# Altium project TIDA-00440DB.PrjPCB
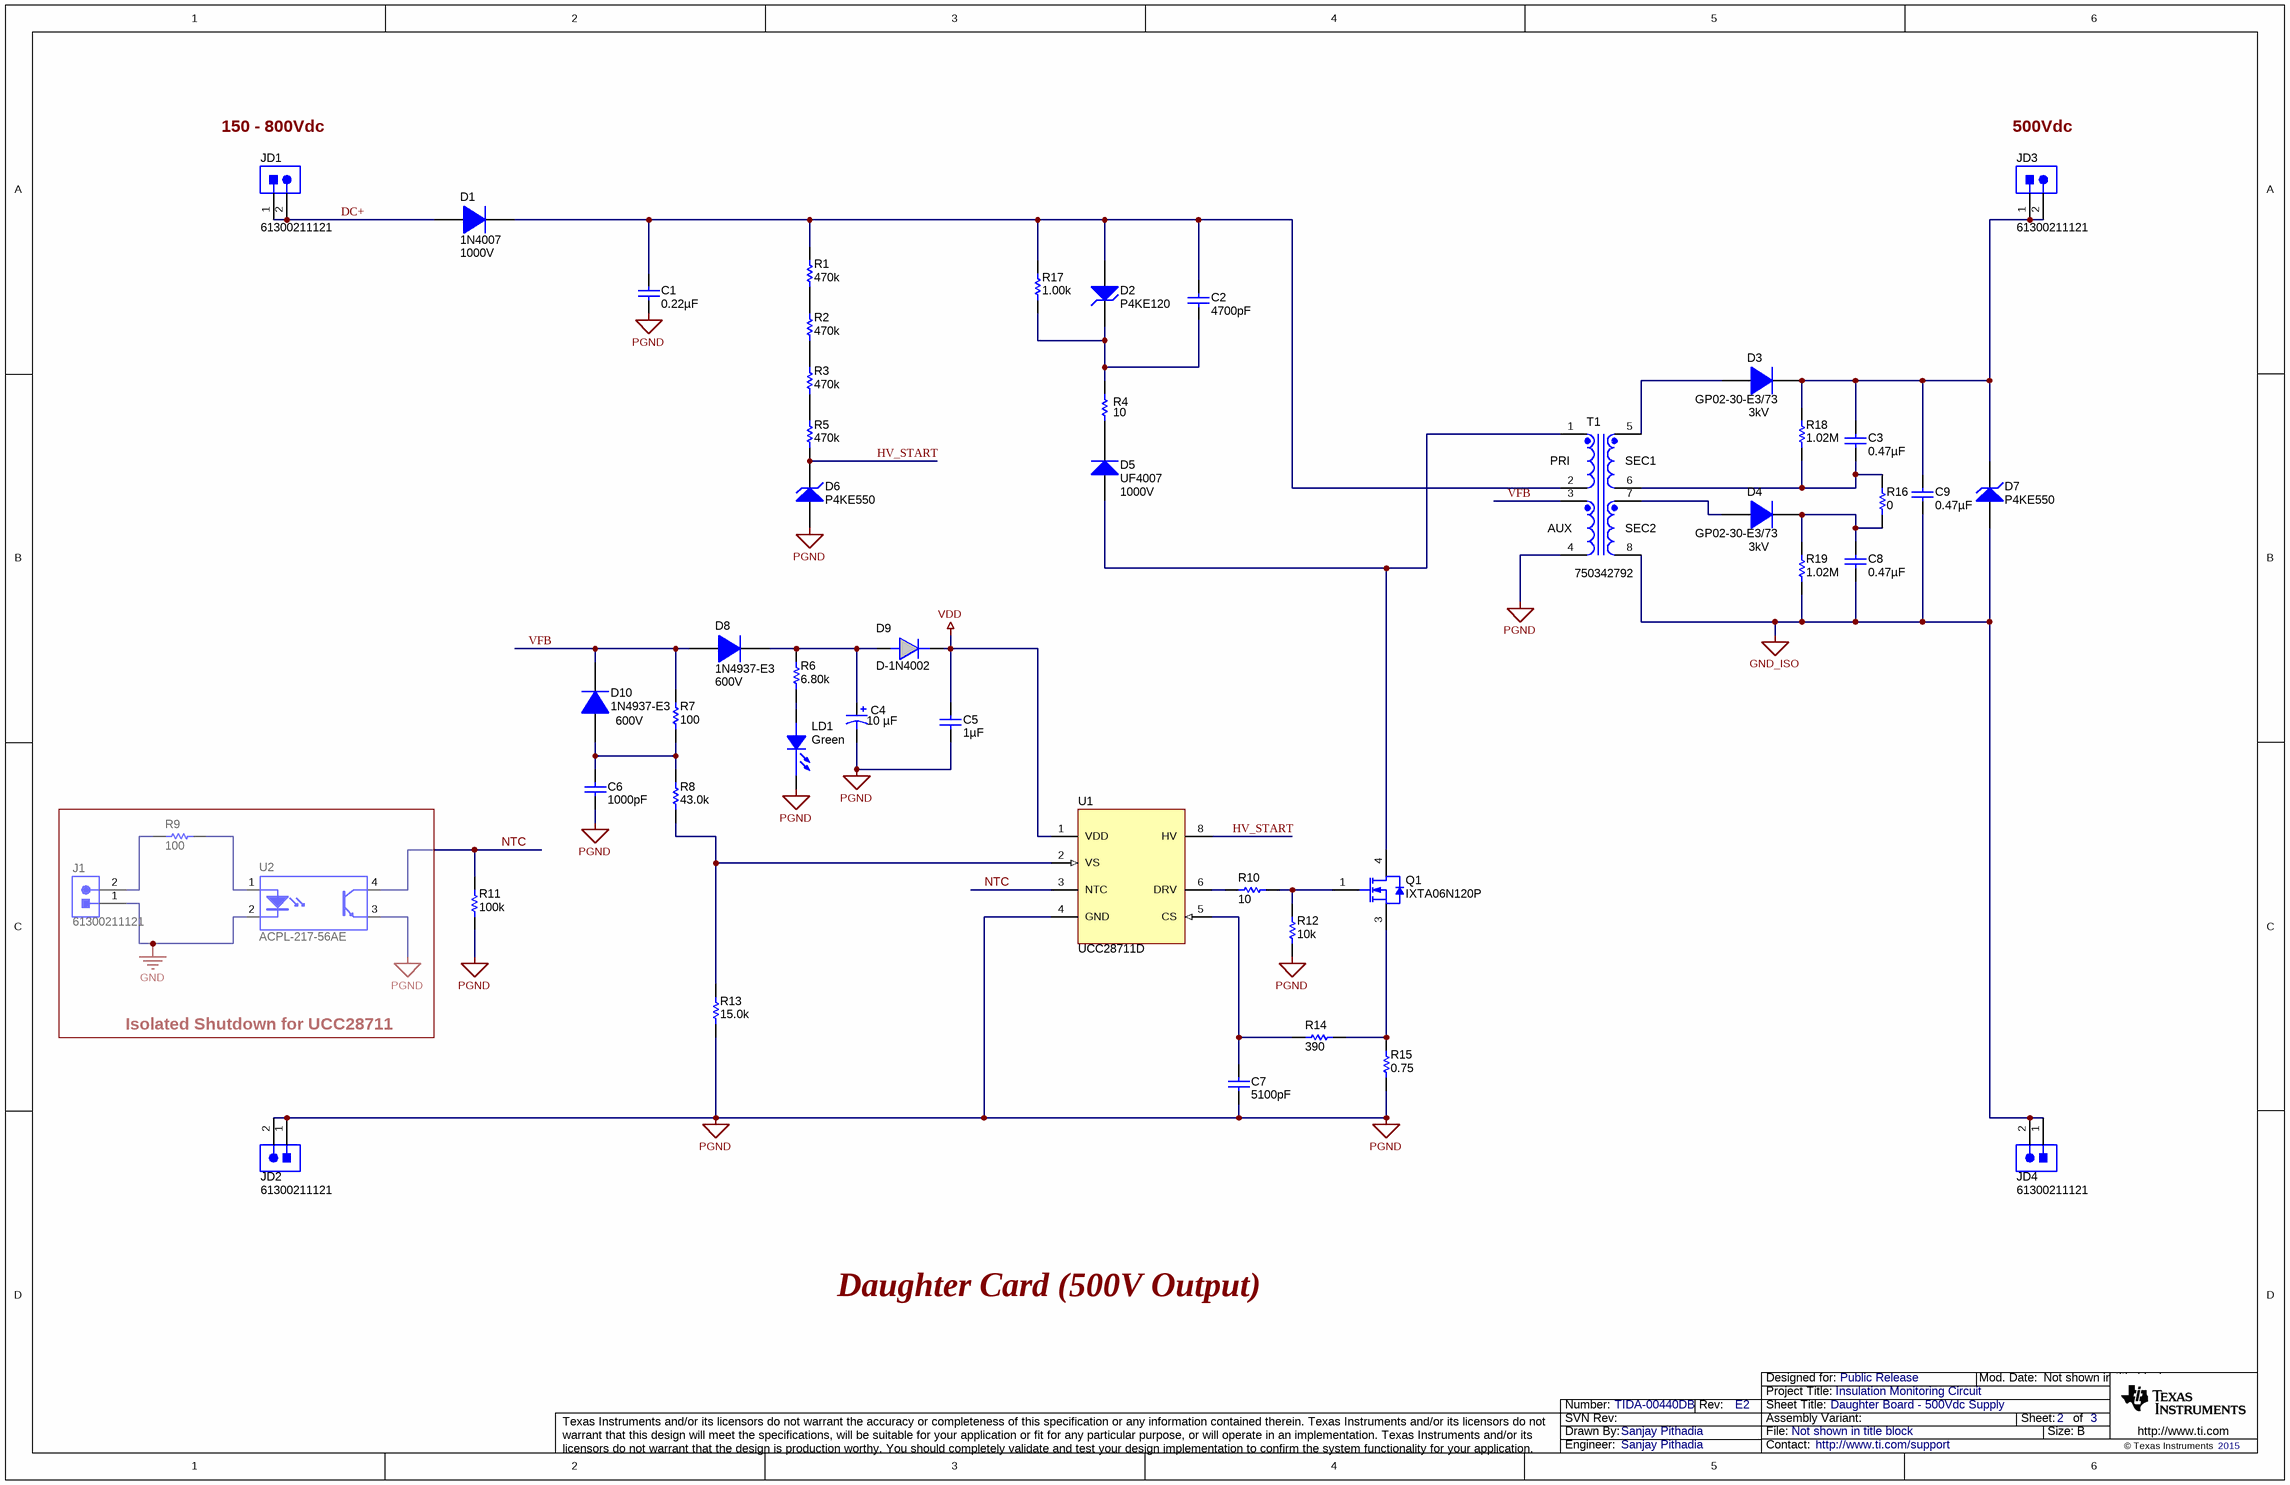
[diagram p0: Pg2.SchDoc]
CopyrightYear: 2015; PCB_Layout: Manjunath M; PCB_Rev: E2; PRJ_Customer: Public Release; PRJ_Engineer: Sanjay Pithadia; PRJ_Number: TIDA-00440DB; PRJ_Title: Insulation Monitoring Circuit; SCH_Rev: E2; TechSupport: http://www.ti.com/support
3 sheets, 56 parts. Net scope: global (net labels, ports and power ports of the same name join across sheets).
Board file: TIDA-00440DB.PcbDoc
Sheets:
  Pg1-Cover.SchDoc
  Pg2.SchDoc
  Pg3_Hardware_ANSI-B.SchDoc

## Sheet Pg1-Cover.SchDoc
size 431 x 279 mm; Date: Not shown in title block; ApprovedBy: Not shown in title block; CheckedBy: Not shown in title block; Author: Not shown in title block; CompanyName: Not shown in title block; DrawnBy: Sanjay Pithadia; Engineer: Not shown in title block; Organization: Not shown in title block; Address1: Not shown in title block; Address2: Not shown in title block; Address3: Not shown in title block; Address4: Not shown in title block; DocumentNumber: 1; Revision: Use project parameter SCH_Rev; SheetNumber: 1; SheetTotal: 3; PageSetup: Record=PageOptions|CenterHorizontal=True|CenterVertical=True|PrintScale=1.00|XCorrection=1.00|YCorrection=1.00|PrintKind=0|BorderSize=5000000|LeftOffset=0|BottomOffset=0|Orientation=2|PaperLength=1000|PaperWidth=1000|Scale=100|PaperSource=15|PrintQuality=600|MediaType=1|DitherType=10|PaperKind=Letter|PrintScaleMode=1

## Sheet Pg2.SchDoc: Daughter Board - 500Vdc Supply
size 431 x 279 mm; Date: Not shown in title block; ApprovedBy: Not shown in title block; CheckedBy: Not shown in title block; Author: Not shown in title block; CompanyName: Not shown in title block; DrawnBy: Sanjay Pithadia; Engineer: Not shown in title block; Organization: Not shown in title block; Address1: Not shown in title block; Address2: Not shown in title block; Address3: Not shown in title block; Address4: Not shown in title block; DocumentNumber: 4; Revision: Use project parameter SCH_Rev; SheetNumber: 2; SheetTotal: 3; PageSetup: Record=PageOptions|CenterHorizontal=True|CenterVertical=True|PrintScale=1.00|XCorrection=1.00|YCorrection=1.00|PrintKind=0|BorderSize=5000000|LeftOffset=0|BottomOffset=0|Orientation=2|PaperLength=1000|PaperWidth=1000|Scale=100|PaperSource=15|PrintQuality=600|MediaType=1|DitherType=10|PaperKind=Letter|PrintScaleMode=1

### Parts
C1  ValueDisplayed: 0.22µF  [B32653_2650x2050x1100]  (hidden comment: B32653A224J)
C2  ValueDisplayed: 4700pF  [1206]  (hidden comment: GRM31BR73A472KW01L)
C3  ValueDisplayed: 0.47µF  [1812]  (hidden comment: C4532X7T2W474K230KA)
C4  ValueDisplayed: 10 µF  [CAPPR2-5x11]  (hidden comment: UVR1V100MDD1TA)
C5  ValueDisplayed: 1µF  [0805_HV]  (hidden comment: GMK212B7105KG-T)
C6  ValueDisplayed: 1000pF  [0805_HV]  (hidden comment: C0805C102K1RACTU)
C7  ValueDisplayed: 5100pF  [0805_HV]  (hidden comment: GRM2195C1H512JA01D)
C8  ValueDisplayed: 0.47µF  [1812]  (hidden comment: C4532X7T2W474K230KA)
C9  ValueDisplayed: 0.47µF  [2220]  (hidden comment: CGA9P1X7T2J474K250KE)
D1  1N4007  value 1000V  [DO-41]
D2  P4KE120  [DO-41]
D3  GP02-30-E3/73  value 3kV  [DO-41]
D4  GP02-30-E3/73  value 3kV  [DO-41]
D5  UF4007  value 1000V  [DO-204AC_VERT]
D6  P4KE550  [DO-41]
D7  P4KE550  [DO-41]
D8  1N4937-E3  value 600V  [DO-41]
D9  D-1N4002  [DO-41]
D10  1N4937-E3  value 600V  [DO-41]
J1  61300211121  [WURTH_61300211121]
JD1  61300211121  [WURTH_61300211121]
JD2  61300211121  [WURTH_61300211121]
JD3  61300211121  [WURTH_61300211121]
JD4  61300211121  [WURTH_61300211121]
LD1  value Green  [LED0603AA]  (hidden comment: LED_LG L29K-G2J1-24-Z)
Q1  IXTA06N120P  [DDPAK]
R1  value 470k  [1206]  (hidden comment: RC1206FR-07470KL)
R2  value 470k  [1206]  (hidden comment: RC1206FR-07470KL)
R3  value 470k  [1206]  (hidden comment: RC1206FR-07470KL)
R4  value 10  [2512M]  (hidden comment: ERJ-1TYJ100U)
R5  value 470k  [1206]  (hidden comment: RC1206FR-07470KL)
R6  value 6.80k  [0805_HV]  (hidden comment: RG2012P-682-B-T5)
R7  ValueDisplayed: 100  [0805_HV]  (hidden comment: CRCW0805100RFKEA)
R8  ValueDisplayed: 43.0k  [0805_HV]  (hidden comment: RG2012P-433-B-T5)
R9  ValueDisplayed: 100  [0805_HV]  (hidden comment: CRCW0805100RFKEA)
R10  ValueDisplayed: 10  [0805_HV]  (hidden comment: CRCW080510R0JNEA)
R11  ValueDisplayed: 100k  [0805_HV]  (hidden comment: CRCW0805100KFKEA)
R12  ValueDisplayed: 10k  [0805_HV]  (hidden comment: CRCW080510K0JNEA)
R13  ValueDisplayed: 15.0k  [0805_HV]  (hidden comment: CRCW080515K0FKEA)
R14  ValueDisplayed: 390  [0805_HV]  (hidden comment: RG2012P-391-B-T5)
R15  ValueDisplayed: 0.75  [2010]  (hidden comment: CSRN2010FKR750)
R16  ValueDisplayed: 0  [1206]  (hidden comment: CRCW12060000Z0EA)
R17  ValueDisplayed: 1.00k  [2512]  (hidden comment: CRCW25121K00FKEG)
R18  ValueDisplayed: 1.02M  [1206]  (hidden comment: CRCW12061M02FKEA)
R19  ValueDisplayed: 1.02M  [1206]  (hidden comment: CRCW12061M02FKEA)
T1  750342792  [Wurth_750342792]
U1  UCC28711D  [D0007A_N]
U2  ACPL-217-56AE  [SO4]

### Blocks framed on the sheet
Isolated Shutdown for UCC28711: J1 R9 U2

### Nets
GND: J1.1 U2.2(K)
GND_ISO: C8.2 C9.2 D7.2(A) JD4.1 JD4.2 R19.1 T1.8
PGND: C1.2 C4.2(-) C5.2 C6.2 C7.2 D6.2(A) JD2.1 JD2.2 LD1.1(C) R11.1 R12.1 R13.1 R15.2 T1.4 U1.4(GND) U2.3(E)
VDD: C5.1 D9.1(C) U1.1(VDD)
DC+: D1.2(A) JD1.1 JD1.2
HV_START: D6.1(K) R5.1 U1.8(HV)
NTC: R11.2 U1.3(NTC) U2.4(C)
VFB: D8.2(A) D10.1(K) R7.2 T1.3
NetC1_1: C1.1 C2.1 D1.1(K) D2.2(A) R1.2 R17.2 T1.2
NetC2_2: C2.2 D2.1(K) R4.2 R17.1
NetC3_1: C3.1 C9.1 D3.1(K) D7.1(K) JD3.1 JD3.2 R18.2
NetC3_2: C3.2 R16.2 R18.1 T1.6
NetC4_1: C4.1(+) D8.1(K) D9.2(A) R6.2
NetC6_1: C6.1 D10.2(A) R7.1 R8.2
NetC7_1: C7.1 R14.1 U1.5(CS)
NetC8_1: C8.1 D4.1(K) R16.1 R19.2
NetD3_2: D3.2(A) T1.5
NetD4_2: D4.2(A) T1.7
NetD5_1: D5.1(K) R4.1
NetD5_2: D5.2(A) Q1.4(D) T1.1
NetJ1_2: J1.2 R9.1
NetLD1_2: LD1.2(A) R6.1
NetQ1_1: Q1.1(G) R10.2 R12.2
NetQ1_3: Q1.3(S) R14.2 R15.1
NetR1_1: R1.1 R2.2
NetR2_1: R2.1 R3.2
NetR3_1: R3.1 R5.2
NetR8_1: R8.1 R13.2 U1.2(VS)
NetR9_2: R9.2 U2.1(A)
NetR10_1: R10.1 U1.6(DRV)

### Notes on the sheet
- 150 - 800Vdc
- 500Vdc
- (near T1) PRI
- (near T1) SEC1
- (near T1) AUX
- (near T1) SEC2
- Daughter Card (500V Output)

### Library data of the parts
C1 = B32653A224J: CAP, Film, 0.22 µF, 1000 V, +/- 5%, TH; Manufacturer: EPCOS Inc; Polarized: N; CompType: Capacitor; Value: 0.22uF; U/M: EA; Cap_F: 0.00000022; Tolerance_%: 5; Value1: Unknown; VDC_V: 1000; Value2: 1000V; TaMin_C: -55; TaMax_C: 110; Cap_Case: 26.5x20.5x11mm
C2 = GRM31BR73A472KW01L: CAP, CERM, 4700pF, 1000V, +/-10%, X7R, 1206; Manufacturer: MuRata; Polarized: N; CompType: Capacitor; U/M: EA; Cap_F: 0.0000000047; Tolerance_%: 10; Value1: Unknown; VDC_V: 1000; TaMin_C: -55; TaMax_C: 125
C3 C8 = GRM43DR72E474KW01L: CAP, CERM, 0.47 µF, 450 V, +/- 10%, X7T, 1812; Manufacturer: TDK Corporation; Polarized: N; CompType: Capacitor; Value: 0.47uF; U/M: EA; Cap_F: 0.00000047; Tolerance_%: 10; Value1: Unknown; VDC_V: 450V; TaMin_C: -55; TaMax_C: 125
C4 = UVR1V100MDD1TA: CAP, AL, 10uF, 35V, +/-20%, TH; Manufacturer: Nichicon; Polarized: Y; CompType: Capacitor; U/M: EA; Cap_F: 0.00001; Tolerance_%: 20; Value1: Unknown; VDC_V: 35; TaMin_C: -40; TaMax_C: 85; Cap_Case: 5x11
C5 = GMK212B7105KG-T: CAP, CERM, 1uF, 35V, +/-10%, X7R, 0805; Manufacturer: Taiyo Yuden; Polarized: N; CompType: Capacitor; U/M: EA; Cap_F: 0.000001; Tolerance_%: 10; Value1: Unknown; VDC_V: 35; TaMin_C: -55; TaMax_C: 125; Cap_Case: 0805
C6 = C0805C102K1RACTU: CAP, CERM, 1000pF, 100V, +/-10%, X7R, 0805; Manufacturer: Kemet; Polarized: N; CompType: Capacitor; U/M: EA; Cap_F: 0.000000001; Tolerance_%: 10; ESR_Ohm: 0.384; Value1: 0.384 ohm; VDC_V: 100; IRMS_A: 0.214; TaMin_C: -55; TaMax_C: 125; Cap_Case: 0805
C7 = GRM2195C1H512JA01D: CAP, CERM, 5100 pF, 50 V, +/- 5%, C0G/NP0, 0805; Manufacturer: MuRata; Polarized: N; CompType: Capacitor; Value: 5100pF; U/M: EA; Cap_F: 0.0000000051; Tolerance_%: 5; Value1: Unknown; VDC_V: 50; Value2: 50V; TaMin_C: -55; TaMax_C: 125; Cap_Case: 0805
C9 = GRM55DR73A104KW01L: CAP, CERM, 0.47 µF, 630 V, +/- 10%, X7T, 2220; Manufacturer: TDK Corporation; Polarized: N; CompType: Capacitor; Value: 0.47uF; U/M: EA; Cap_F: 0.0000001; Tolerance_%: 10; Value1: Unknown; VDC_V: 630V; TempCo: X7R; TaMin_C: -55; TaMax_C: 125
D1 = 1N4007: Diode, P-N, 1000V, 1A, TH; Manufacturer: Fairchild Semiconductor; U/M: EA; Vf_V: 1.1; Value2: 1.1V; Io_A: 1; Vr_V: 1000; TJmax_C: 175; RJC_CperW: 50
D2 = P4KE550: TVS DIODE; Manufacturer: Littelfuse Inc; CompType: Zener; Value: 102V
D3 D4 = 1N4007: Diode, P-N, 3000V, 0.25A, TH; Manufacturer: Vishay; Io_A: 1
D5 = UF4007: DIODE FAST REC 1KV 1A DO41; Manufacturer: Fairchild Semiconductor
D6 D7 = P4KE550: TVS DIODE 495VWM 798VC AXIAL; Manufacturer: Littelfuse Inc; CompType: Zener; Value: 495V
D8 D10 = 1N4937-E3: Diode, Switching, 600V, 1A, TH; Manufacturer: Vishay-Semiconductor; U/M: EA; Vf_V: 1.2; Value2: 1.2V; Io_A: 1; Vr_V: 600; TJmax_C: 150; RJC_CperW: 25
D9 = D-1N4002: Diode, Signal, 100V, 1A; PartNumber: 1N4002; Manufacturer: Diodes; Area: 54000; Value: 1N4002
J1 JD1-JD4 = 61300211121: Header, 2.54 mm, 2x1, Gold, TH; Manufacturer: Wurth Elektronik eiSos; SymbolCreator: a0412235; U/M: EA
LD1 = LED_LG L29K-G2J1-24-Z: LED SmartLED Green 570NM; Manufacturer: OSRAM; SymbolCreator: x0120606
Q1 = IXTA06N120P: MOSFET, N-CH, 1200 V, 0.6 A, DDPAK; Manufacturer: IXYS; Alternate Manufacturer: None; U/M: EA; ChType: N; Value: 1200V; VdsMax_V: 1200; Value1: ? ohm; Value2: 13.3 nC; QgTyp_nC: 13.3; Vgs_V: 20; IdsMax_A: 0.6
R1-R3 R5 = RC1206FR-07470KL: RES, 470k ohm, 1%, 0.25W, 1206; Manufacturer: Yageo America; CompType: Resistor; Res_ohm: 470000; Tolerance_%: 1; Power_W: 0.25; VDC_V: 200; TempCo: 100 ppm/C; U/M: EA
R4 = ERJ-1TYJ100U: RES, 10 ohm, 5%, 1W, 2512; Manufacturer: Panasonic; CompType: Resistor; Value_Code: 10R0; Tolerance_%: 5; Power_W: 1; VDC_V: 200; TempCo: 200 ppm/C; EIA_Code: E24; U/M: EA
R6 = RG2012P-682-B-T5: RES, 6.80k ohm, 0.1%, 0.125W, 0805; Manufacturer: Susumu Co Ltd; CompType: Resistor; Res_ohm: 6800; Value_Code: 6k80; Tolerance_%: 0.1; Power_W: 0.125; VDC_V: 100; TempCo: 25 ppm/C; U/M: EA
R7 R9 = CRCW0805100RFKEA: RES, 100, 1%, 0.125 W, 0805; Manufacturer: Vishay-Dale; CompType: Resistor; Value: 100; Value_Code: 100R; Tolerance_%: 1; Power_W: 0.125; Value2: 0.125W; VDC_V: 150; TempCo: 100 ppm/C; EIA_Code: E96; U/M: EA
R8 = RG2012P-433-B-T5: RES, 43.0 k, 0.1%, 0.125 W, 0805; Manufacturer: Susumu Co Ltd; CompType: Resistor; Value: 43.0k; Res_ohm: 43000; Value_Code: 43k0; Tolerance_%: 0.1; Power_W: 0.125; Value2: 0.125W; VDC_V: 100; TempCo: 25 ppm/C; U/M: EA
R10 = CRCW080510R0JNEA: RES, 10, 5%, 0.125 W, 0805; Manufacturer: Vishay-Dale; CompType: Resistor; Value: 10; Value_Code: 10R0; Tolerance_%: 5; Power_W: 0.125; Value2: 0.125W; VDC_V: 150; TempCo: 200 ppm/C; EIA_Code: E24; U/M: EA
R11 = CRCW0805100KFKEA: RES, 100 k, 1%, 0.125 W, 0805; Manufacturer: Vishay-Dale; CompType: Resistor; Value: 100k; Res_ohm: 100000; Tolerance_%: 1; Power_W: 0.125; Value2: 0.125W; VDC_V: 150; TempCo: 100 ppm/C; EIA_Code: E96; U/M: EA
R12 = CRCW080510K0JNEA: RES, 10 k, 5%, 0.125 W, 0805; Manufacturer: Vishay-Dale; CompType: Resistor; Value: 10k; Res_ohm: 10000; Value_Code: 10k0; Tolerance_%: 5; Power_W: 0.125; Value2: 0.125W; VDC_V: 150; TempCo: 200 ppm/C; EIA_Code: E24; U/M: EA
R13 = CRCW080515K0FKEA: RES, 15.0 k, 1%, 0.125 W, 0805; Manufacturer: Vishay-Dale; CompType: Resistor; Value: 15.0k; Res_ohm: 15000; Value_Code: 15k0; Tolerance_%: 1; Power_W: 0.125; Value2: 0.125W; VDC_V: 150; TempCo: 100 ppm/C; EIA_Code: E96; U/M: EA
R14 = RG2012P-391-B-T5: RES, 390, 0.1%, 0.125 W, 0805; Manufacturer: Susumu Co Ltd; CompType: Resistor; Value: 390; Value_Code: 390R; Tolerance_%: 0.1; Power_W: 0.125; Value2: 0.125W; VDC_V: 100; TempCo: 25 ppm/C; U/M: EA
R15 = CSRN2010FKR750: RES, 0.75, 1%, 1 W, 2010; Manufacturer: Stackpole Electronics Inc; CompType: Resistor; Value: 0.75; Value_Code: R750; Tolerance_%: 1; Value2: 1W; TempCo: 250 ppm/C; EIA_Code: E96; U/M: EA
R16 = CRCW12060000Z0EA: RES, 0, 5%, 0.25 W, 1206; Manufacturer: Vishay-Dale; CompType: Resistor; Value: 0; Value_Code: 0000; Tolerance_%: 5; Power_W: 0.25; Value2: 0.25W; VDC_V: 200; TempCo: 200 ppm/C; EIA_Code: E24; U/M: EA
R17 = CRCW25121K00FKEG: RES, 1.00 k, 1%, 1 W, 2512; Manufacturer: Vishay-Dale; CompType: Resistor; Value: 1.00k; Res_ohm: 1000; Value_Code: 1k00; Tolerance_%: 1; Value2: 1W; VDC_V: 500; TempCo: 100 ppm/C; EIA_Code: E96; U/M: EA
R18 R19 = CRCW12061M02FKEA: RES, 1.02 M, 1%, 0.25 W, 1206; Manufacturer: Vishay-Dale; CompType: Resistor; Value: 1.02Meg; Res_ohm: 1020000; Value_Code: 1M02; Tolerance_%: 1; Power_W: 0.25; Value2: 0.25W; VDC_V: 200; TempCo: 100 ppm/C; EIA_Code: E96; U/M: EA
T1 = 750342792: Transformer, 738uH, SMT; Manufacturer: Wurth Elektronik eiSos; SymbolCreator: a0411947; DCR_Ohm: 1.177; LeakageL: 45uH; U/M: EA
U1 = UCC28711D: IC REG CTRLR FLYBK ISO 7SOIC; Manufacturer: Texas Instruments
U2 = ACPL-217-56AE: Optocoupler, DC Input ,Half-Pitch Phototransistor, 3000 VRMS, SO-4; Manufacturer: Avago; CompType: Photocoupler; U/M: EA

## Sheet Pg3_Hardware_ANSI-B.SchDoc
size 431 x 279 mm; Date: Not shown in title block; ApprovedBy: Not shown in title block; CheckedBy: Not shown in title block; Author: Not shown in title block; CompanyName: Not shown in title block; Engineer: Not shown in title block; Organization: Not shown in title block; Address1: Not shown in title block; Address2: Not shown in title block; Address3: Not shown in title block; Address4: Not shown in title block; DocumentNumber: 5; Revision: Use project parameter SCH_Rev; SheetNumber: 3; SheetTotal: 3; PageSetup: Record=PageOptions|CenterHorizontal=True|CenterVertical=True|PrintScale=1.00|XCorrection=1.00|YCorrection=1.00|PrintKind=0|BorderSize=5000000|LeftOffset=0|BottomOffset=0|Orientation=2|PaperLength=1000|PaperWidth=1000|Scale=100|PaperSource=15|PrintQuality=600|MediaType=1|DitherType=10|PaperKind=Letter|PrintScaleMode=1
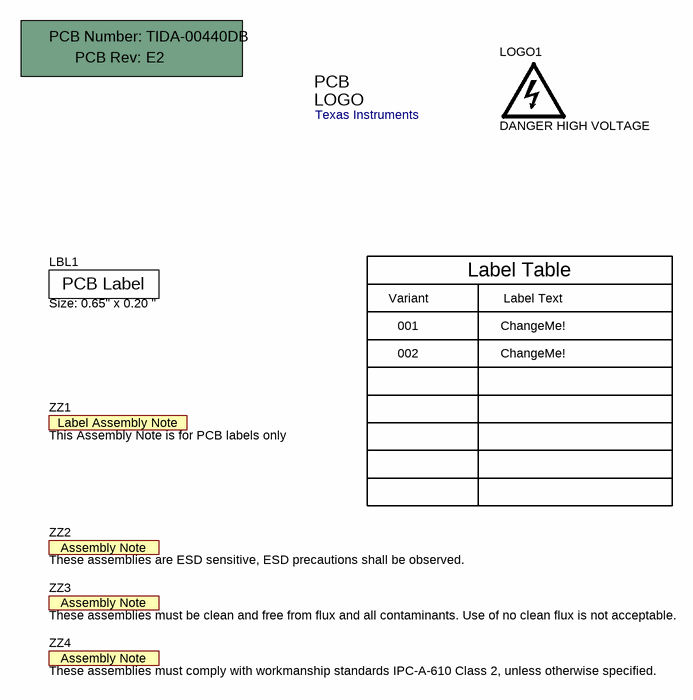
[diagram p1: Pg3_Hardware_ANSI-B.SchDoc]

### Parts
!PCB1  Printed Circuit Board  (value not drawn)  (mechanical)
LBL1  Size: 0.65" x 0.20 "  [Label_650x200]
LOGO1  DANGER HIGH VOLTAGE  [IEC_HighVoltage_Large]  (no BOM)
Logo2  Texas Instruments  [TI_Stacked_Overlay_Medium]  (no BOM)
ZZ1  This Assembly Note is for PCB labels only  [AssemblyNoteLabel]  (no BOM)
ZZ2  These assemblies are ESD sensitive, ESD precautions shall be observed.  [AssemblyNote]  (no BOM)
ZZ3  These assemblies must be clean and free from flux and all contaminants. Use of no clean flux is not acceptable.  [AssemblyNote]  (no BOM)
ZZ4  These assemblies must comply with workmanship standards IPC-A-610 Class 2, unless otherwise specified.  [AssemblyNote]  (no BOM)

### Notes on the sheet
- Variant
- Label Table
- Label Text
- 001
- 002
- ChangeMe!

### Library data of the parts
!PCB1 = PCB: Manufacturer: Any; PartNumber: TIDA-00440DB; SymbolCreator: a0412235
LBL1 = THT-14-423-10: Thermal Transfer Printable Labels, 0.650" W x 0.200" H - 10,000 per roll; Manufacturer: Brady; SymbolCreator: a0412235; CompType: Label
LOGO1 = IEC_HighVoltage: IEC 61010-1 High Voltage Warning; SymbolCreator: a0412235
Logo2 = TI_Logo: Texas Instrument Corporate Signature; SymbolCreator: a0412235
ZZ1 = AssemblyNoteLabel: SymbolCreator: a0412235
ZZ2-ZZ4 = AssemblyNote: SymbolCreator: codlsc

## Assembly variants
001: not fitted C6 D10 R17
